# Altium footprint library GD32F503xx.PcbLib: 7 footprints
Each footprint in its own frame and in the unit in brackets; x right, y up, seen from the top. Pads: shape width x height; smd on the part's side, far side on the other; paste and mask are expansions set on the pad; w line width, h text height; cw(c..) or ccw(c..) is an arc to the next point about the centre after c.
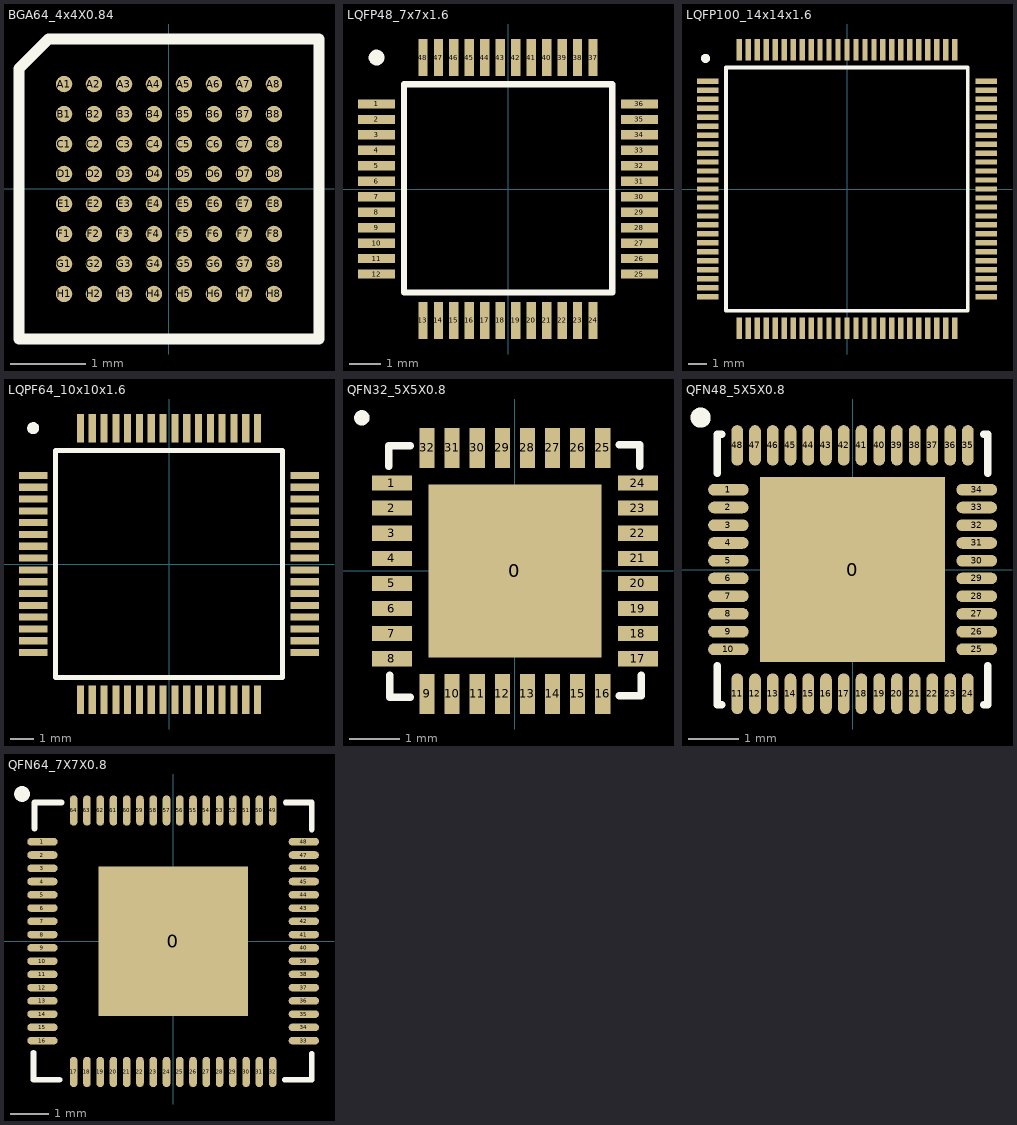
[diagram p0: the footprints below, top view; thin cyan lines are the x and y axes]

## BGA64_4x4X0.84 [mm]
pads (64):
  round 0.22 smd mask+0.05: A1(-1.4,1.4) A2(-1,1.4) A3(-0.6,1.4) A4(-0.2,1.4) A5(0.2,1.4) A6(0.6,1.4) A7(1,1.4) A8(1.4,1.4) B1(-1.4,1) B2(-1,1) B3(-0.6,1) B4(-0.2,1) B5(0.2,1) B6(0.6,1) B7(1,1) B8(1.4,1) C1(-1.4,0.6) C2(-1,0.6) C3(-0.6,0.6) C4(-0.2,0.6) C5(0.2,0.6) C6(0.6,0.6) C7(1,0.6) C8(1.4,0.6) D1(-1.4,0.2) D2(-1,0.2) D3(-0.6,0.2) D4(-0.2,0.2) D5(0.2,0.2) D6(0.6,0.2) D7(1,0.2) D8(1.4,0.2) E1(-1.4,-0.2) E2(-1,-0.2) E3(-0.6,-0.2) E4(-0.2,-0.2) E5(0.2,-0.2) E6(0.6,-0.2) E7(1,-0.2) E8(1.4,-0.2) F1(-1.4,-0.6) F2(-1,-0.6) F3(-0.6,-0.6) F4(-0.2,-0.6) F5(0.2,-0.6) F6(0.6,-0.6) F7(1,-0.6) F8(1.4,-0.6) G1(-1.4,-1) G2(-1,-1) G3(-0.6,-1) G4(-0.2,-1) G5(0.2,-1) G6(0.6,-1) G7(1,-1) G8(1.4,-1) H1(-1.4,-1.4) H2(-1,-1.4) H3(-0.6,-1.4) H4(-0.2,-1.4) H5(0.2,-1.4) H6(0.6,-1.4) H7(1,-1.4) H8(1.4,-1.4)
Top Overlay:
  lines w0.152: -2,-2 2,-2 2,2 -1.607,2 -2,1.607 -2,-2
3D body "BGA64C40P8X8_400X400X84.step": height 0.84, standoff 0, extent -2,-2 2,2

## LQFP48_7x7x1.6 [mm]
pads (48):
  rect 1.2x0.3 smd: 1(-4.25,2.75) 2(-4.25,2.25) 3(-4.25,1.75) 4(-4.25,1.25) 5(-4.25,0.75) 6(-4.25,0.25) 7(-4.25,-0.25) 8(-4.25,-0.75) 9(-4.25,-1.25) 10(-4.25,-1.75) 11(-4.25,-2.25) 12(-4.25,-2.75) 25(4.25,-2.75) 26(4.25,-2.25) 27(4.25,-1.75) 28(4.25,-1.25) 29(4.25,-0.75) 30(4.25,-0.25) 31(4.25,0.25) 32(4.25,0.75) 33(4.25,1.25) 34(4.25,1.75) 35(4.25,2.25) 36(4.25,2.75)
  rect 0.3x1.2 smd: 13(-2.75,-4.25) 14(-2.25,-4.25) 15(-1.75,-4.25) 16(-1.25,-4.25) 17(-0.75,-4.25) 18(-0.25,-4.25) 19(0.25,-4.25) 20(0.75,-4.25) 21(1.25,-4.25) 22(1.75,-4.25) 23(2.25,-4.25) 24(2.75,-4.25) 37(2.75,4.25) 38(2.25,4.25) 39(1.75,4.25) 40(1.25,4.25) 41(0.75,4.25) 42(0.25,4.25) 43(-0.25,4.25) 44(-0.75,4.25) 45(-1.25,4.25) 46(-1.75,4.25) 47(-2.25,4.25) 48(-2.75,4.25)
Top Overlay:
  circle w0.254: c-4.25,4.25 r0.127
  lines w0.203: -3.361,-3.346 -3.361,3.385 3.37,3.385 3.37,-3.346 -3.361,-3.346
3D body "TSQFP50P900X900X160-48N.step": height 1.6, standoff 0, extent -4.5,-4.5 4.5,4.5

## LQFP100_14x14x1.6 [mm]
pads (100):
  rect 1.2x0.3 smd: 1(-7.75,6) 2(-7.75,5.5) 3(-7.75,5) 4(-7.75,4.5) 5(-7.75,4) 6(-7.75,3.5) 7(-7.75,3) 8(-7.75,2.5) 9(-7.75,2) 10(-7.75,1.5) 11(-7.75,1) 12(-7.75,0.5) 13(-7.75,0) 14(-7.75,-0.5) 15(-7.75,-1) 16(-7.75,-1.5) 17(-7.75,-2) 18(-7.75,-2.5) 19(-7.75,-3) 20(-7.75,-3.5) 21(-7.75,-4) 22(-7.75,-4.5) 23(-7.75,-5) 24(-7.75,-5.5) 25(-7.75,-6) 51(7.75,-6) 52(7.75,-5.5) 53(7.75,-5) 54(7.75,-4.5) 55(7.75,-4) 56(7.75,-3.5) 57(7.75,-3) 58(7.75,-2.5) 59(7.75,-2) 60(7.75,-1.5) 61(7.75,-1) 62(7.75,-0.5) 63(7.75,0) 64(7.75,0.5) 65(7.75,1) 66(7.75,1.5) 67(7.75,2) 68(7.75,2.5) 69(7.75,3) 70(7.75,3.5) 71(7.75,4) 72(7.75,4.5) 73(7.75,5) 74(7.75,5.5) 75(7.75,6)
  rect 0.3x1.2 smd: 26(-6,-7.75) 27(-5.5,-7.75) 28(-5,-7.75) 29(-4.5,-7.75) 30(-4,-7.75) 31(-3.5,-7.75) 32(-3,-7.75) 33(-2.5,-7.75) 34(-2,-7.75) 35(-1.5,-7.75) 36(-1,-7.75) 37(-0.5,-7.75) 38(0,-7.75) 39(0.5,-7.75) 40(1,-7.75) 41(1.5,-7.75) 42(2,-7.75) 43(2.5,-7.75) 44(3,-7.75) 45(3.5,-7.75) 46(4,-7.75) 47(4.5,-7.75) 48(5,-7.75) 49(5.5,-7.75) 50(6,-7.75) 76(6,7.75) 77(5.5,7.75) 78(5,7.75) 79(4.5,7.75) 80(4,7.75) 81(3.5,7.75) 82(3,7.75) 83(2.5,7.75) 84(2,7.75) 85(1.5,7.75) 86(1,7.75) 87(0.5,7.75) 88(0,7.75) 89(-0.5,7.75) 90(-1,7.75) 91(-1.5,7.75) 92(-2,7.75) 93(-2.5,7.75) 94(-3,7.75) 95(-3.5,7.75) 96(-4,7.75) 97(-4.5,7.75) 98(-5,7.75) 99(-5.5,7.75) 100(-6,7.75)
Top Overlay:
  circle w0.254: c-7.877,7.27 r0.127
  lines w0.203: -6.734,-6.782 6.728,-6.782 6.728,6.762 -6.734,6.762 -6.734,-6.782
3D body "TSQFP50P1600X1600X160-100N.step": height 1.6, standoff 0, extent -8,-8 8,8

## LQPF64_10x10x1.6 [mm]
pads (64):
  rect 1.2x0.3 smd: 1(-5.75,3.75) 2(-5.75,3.25) 3(-5.75,2.75) 4(-5.75,2.25) 5(-5.75,1.75) 6(-5.75,1.25) 7(-5.75,0.75) 8(-5.75,0.25) 9(-5.75,-0.25) 10(-5.75,-0.75) 11(-5.75,-1.25) 12(-5.75,-1.75) 13(-5.75,-2.25) 14(-5.75,-2.75) 15(-5.75,-3.25) 16(-5.75,-3.75) 33(5.75,-3.75) 34(5.75,-3.25) 35(5.75,-2.75) 36(5.75,-2.25) 37(5.75,-1.75) 38(5.75,-1.25) 39(5.75,-0.75) 40(5.75,-0.25) 41(5.75,0.25) 42(5.75,0.75) 43(5.75,1.25) 44(5.75,1.75) 45(5.75,2.25) 46(5.75,2.75) 47(5.75,3.25) 48(5.75,3.75)
  rect 0.3x1.2 smd: 17(-3.75,-5.75) 18(-3.25,-5.75) 19(-2.75,-5.75) 20(-2.25,-5.75) 21(-1.75,-5.75) 22(-1.25,-5.75) 23(-0.75,-5.75) 24(-0.25,-5.75) 25(0.25,-5.75) 26(0.75,-5.75) 27(1.25,-5.75) 28(1.75,-5.75) 29(2.25,-5.75) 30(2.75,-5.75) 31(3.25,-5.75) 32(3.75,-5.75) 49(3.75,5.75) 50(3.25,5.75) 51(2.75,5.75) 52(2.25,5.75) 53(1.75,5.75) 54(1.25,5.75) 55(0.75,5.75) 56(0.25,5.75) 57(-0.25,5.75) 58(-0.75,5.75) 59(-1.25,5.75) 60(-1.75,5.75) 61(-2.25,5.75) 62(-2.75,5.75) 63(-3.25,5.75) 64(-3.75,5.75)
Top Overlay:
  circle w0.254: c-5.75,5.75 r0.127
  lines w0.203: -4.801,-4.801 4.801,-4.801 4.801,4.801 -4.801,4.801 -4.801,-4.801
3D body "TSQFP50P1200X1200X160-64N.step": height 1.6, standoff 0, extent -6,-6 6,6

## QFN32_5X5X0.8 [mm]
pads (33):
  rect 3.45x3.45 smd: 0(0,0)
  rect 0.8x0.3 smd: 1(-2.45,1.75) 2(-2.45,1.25) 3(-2.45,0.75) 4(-2.45,0.25) 5(-2.45,-0.25) 6(-2.45,-0.75) 7(-2.45,-1.25) 8(-2.45,-1.75) 17(2.45,-1.75) 18(2.45,-1.25) 19(2.45,-0.75) 20(2.45,-0.25) 21(2.45,0.25) 22(2.45,0.75) 23(2.45,1.25) 24(2.45,1.75)
  rect 0.3x0.8 smd: 9(-1.75,-2.45) 10(-1.25,-2.45) 11(-0.75,-2.45) 12(-0.25,-2.45) 13(0.25,-2.45) 14(0.75,-2.45) 15(1.25,-2.45) 16(1.75,-2.45) 25(1.75,2.45) 26(1.25,2.45) 27(0.75,2.45) 28(0.25,2.45) 29(-0.25,2.45) 30(-0.75,2.45) 31(-1.25,2.45) 32(-1.75,2.45)
Top Overlay:
  circle w0.152: c-3.048,3.048 r0.076
  lines w0.152: -2.515,2.083 -2.515,2.489 -2.083,2.489 ; -2.489,-2.083 -2.489,-2.515 -2.083,-2.515 ; 2.083,-2.489 2.515,-2.489 2.515,-2.083 ; 2.083,2.515 2.489,2.515 2.489,2.083
3D body "QFN50P500X500X80_HS-33N.step": height 0.8, standoff 0, extent -2.551,-2.551 2.551,2.551

## QFN48_5X5X0.8 [mm]
pads (49):
  rect 3.65x3.65 smd: 0(0,0)
  oval 0.8x0.23 smd: 1(-2.45,1.575) 2(-2.45,1.225) 3(-2.45,0.875) 4(-2.45,0.525) 5(-2.45,0.175) 6(-2.45,-0.175) 7(-2.45,-0.525) 8(-2.45,-0.875) 9(-2.45,-1.225) 10(-2.45,-1.575) 25(2.45,-1.575) 26(2.45,-1.225) 27(2.45,-0.875) 28(2.45,-0.525) 29(2.45,-0.175) 30(2.45,0.175) 31(2.45,0.525) 32(2.45,0.875) 33(2.45,1.225) 34(2.45,1.575)
  oval 0.23x0.8 smd: 11(-2.275,-2.45) 12(-1.925,-2.45) 13(-1.575,-2.45) 14(-1.225,-2.45) 15(-0.875,-2.45) 16(-0.525,-2.45) 17(-0.175,-2.45) 18(0.175,-2.45) 19(0.525,-2.45) 20(0.875,-2.45) 21(1.225,-2.45) 22(1.575,-2.45) 23(1.925,-2.45) 24(2.275,-2.45) 35(2.275,2.45) 36(1.925,2.45) 37(1.575,2.45) 38(1.225,2.45) 39(0.875,2.45) 40(0.525,2.45) 41(0.175,2.45) 42(-0.175,2.45) 43(-0.525,2.45) 44(-0.875,2.45) 45(-1.225,2.45) 46(-1.575,2.45) 47(-1.925,2.45) 48(-2.275,2.45)
Top Overlay:
  circle w0.254: c-2.997,2.997 r0.072
  lines w0.152: -2.667,-1.905 -2.667,-2.667 -2.587,-2.667 ; -2.667,1.905 -2.667,2.667 -2.587,2.667 ; 2.587,-2.667 2.667,-2.667 2.667,-1.905 ; 2.587,2.667 2.667,2.667 2.667,1.905
3D body "QFN35P500X500X80_HS-49N.step": height 0.8, standoff 0, extent -2.551,-2.551 2.551,2.551

## QFN64_7X7X0.8 [mm]
pads (65):
  rect 3.95x3.95 smd: 0(0,0)
  oval 0.8x0.2 smd: 1(-3.45,2.625) 2(-3.45,2.275) 3(-3.45,1.925) 4(-3.45,1.575) 5(-3.45,1.225) 6(-3.45,0.875) 7(-3.45,0.525) 8(-3.45,0.175) 9(-3.45,-0.175) 10(-3.45,-0.525) 11(-3.45,-0.875) 12(-3.45,-1.225) 13(-3.45,-1.575) 14(-3.45,-1.925) 15(-3.45,-2.275) 16(-3.45,-2.625) 33(3.45,-2.625) 34(3.45,-2.275) 35(3.45,-1.925) 36(3.45,-1.575) 37(3.45,-1.225) 38(3.45,-0.875) 39(3.45,-0.525) 40(3.45,-0.175) 41(3.45,0.175) 42(3.45,0.525) 43(3.45,0.875) 44(3.45,1.225) 45(3.45,1.575) 46(3.45,1.925) 47(3.45,2.275) 48(3.45,2.625)
  oval 0.2x0.8 smd: 17(-2.625,-3.45) 18(-2.275,-3.45) 19(-1.925,-3.45) 20(-1.575,-3.45) 21(-1.225,-3.45) 22(-0.875,-3.45) 23(-0.525,-3.45) 24(-0.175,-3.45) 25(0.175,-3.45) 26(0.525,-3.45) 27(0.875,-3.45) 28(1.225,-3.45) 29(1.575,-3.45) 30(1.925,-3.45) 31(2.275,-3.45) 32(2.625,-3.45) 49(2.625,3.45) 50(2.275,3.45) 51(1.925,3.45) 52(1.575,3.45) 53(1.225,3.45) 54(0.875,3.45) 55(0.525,3.45) 56(0.175,3.45) 57(-0.175,3.45) 58(-0.525,3.45) 59(-0.875,3.45) 60(-1.225,3.45) 61(-1.575,3.45) 62(-1.925,3.45) 63(-2.275,3.45) 64(-2.625,3.45)
Top Overlay:
  circle w0.254: c-3.988,3.886 r0.08
  lines w0.152: -3.683,-2.946 -3.683,-3.658 -2.997,-3.658 ; -3.658,2.972 -3.658,3.658 -2.946,3.658 ; 2.946,-3.658 3.658,-3.658 3.658,-2.972 ; 2.972,3.658 3.658,3.658 3.658,2.946
3D body "QFN35P700X700X80_HS-65N.step": height 0.8, standoff 0, extent -3.551,-3.551 3.551,3.551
